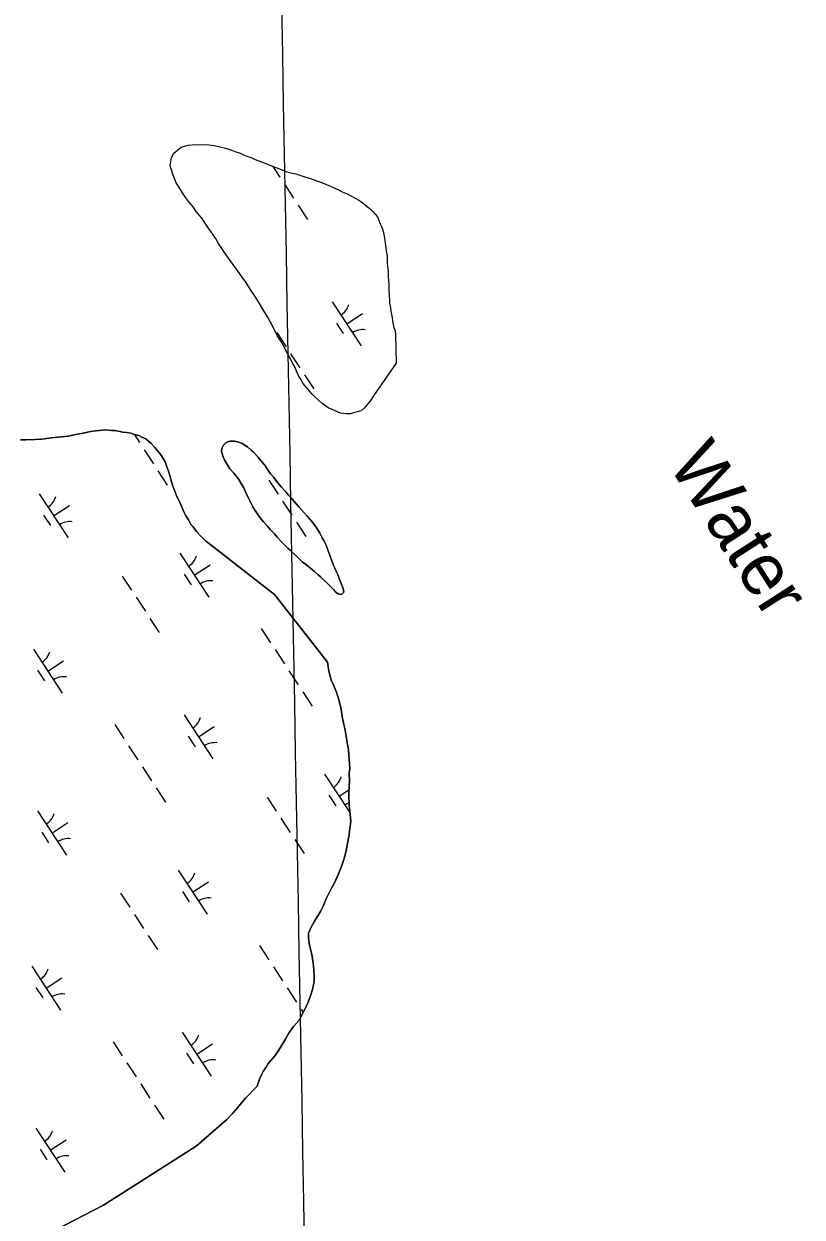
# Model space of a CAD drawing. Extents: x 3945642 to 3966284, y 206476 to 228921.
# Drawn here: x 3956647 to 3957386, y 220127 to 221259 of the extents above; entities that cross this region are included whole.
import ezdxf

# ---------------------------------------------------------------- set-up
doc = ezdxf.new("R2010")
doc.units = 0
for name, color, linetype in [('V-GRID-MAJR', 7, 'Continuous'), ('V-RIVR-IDEN', 7, 'Continuous'), ('V-TOPO-SHOR', 7, 'Continuous'), ('V-WETL-SWMP', 7, 'Continuous')]:
    doc.layers.add(name, color=color, linetype=linetype)

msp = doc.modelspace()

# ---------------------------------------------------------------- linework, layer by layer
at = {"layer": 'V-GRID-MAJR'}
msp.add_spline([(3957114.3, 209221.5), (3957056.9, 212329.8), (3956944.9, 218389.8), (3956833, 224449.7), (3956787.8, 226894.5)], degree=3, dxfattribs=at)
at = {"layer": 'V-TOPO-SHOR'}
msp.add_line((3956884.6, 220717.6), (3956821.6, 220766.8), dxfattribs=at)
for points in [[(3957000.3, 220937.3), (3956978.8, 220906.3), (3956975.2, 220901), (3956972.9, 220898.3), (3956969.9, 220894.7), (3956967, 220892), (3956963.4, 220891), (3956959.8, 220890), (3956956.8, 220889.3), (3956952.9, 220889.3), (3956947.3, 220889.9), (3956942.3, 220891.9), (3956939.3, 220893.2), (3956935.7, 220894.8), (3956929.8, 220899.1), (3956923.1, 220905.3), (3956920.5, 220907.9), (3956916.8, 220911.8), (3956914.9, 220914.1), (3956911.5, 220918.4), (3956909.9, 220921.3), (3956907.5, 220925.6), (3956905.5, 220929.8), (3956904.2, 220933.1), (3956902.2, 220937.1), (3956896.9, 220946.6), (3956891.6, 220956.8), (3956887.2, 220963.6), (3956884.6, 220968.9), (3956880.9, 220976.1), (3956877.9, 220981.4), (3956873.6, 220988.6), (3956870.3, 220993.8), (3956865.6, 221001.4), (3956862.3, 221006.6), (3956857.7, 221013.8), (3956854.7, 221018.1), (3956851.7, 221022), (3956847, 221028.6), (3956843.4, 221033.5), (3956838.7, 221040), (3956835.8, 221044.3), (3956831.4, 221050.9), (3956828.5, 221055.8), (3956822.1, 221065.3), (3956818.8, 221070.2), (3956815.5, 221074.8), (3956810.2, 221081.4), (3956807.5, 221085.6), (3956803.2, 221090.5), (3956800.6, 221094.1), (3956796.6, 221100), (3956793.9, 221104.6), (3956791.3, 221108.6), (3956788.3, 221115.8), (3956786.6, 221121.7), (3956785.6, 221124.7), (3956786.2, 221128.6), (3956786.9, 221132.6), (3956789.1, 221136.5), (3956792.4, 221139.5), (3956796, 221142.2), (3956799.3, 221143.2), (3956802.6, 221144.2), (3956809.2, 221144.9), (3956813.8, 221144.6), (3956817.4, 221144.9), (3956822.7, 221144.6), (3956827.3, 221144), (3956832.9, 221142.7), (3956838.2, 221141.4), (3956841.4, 221140.5), (3956848, 221137.9), (3956851.3, 221136.9), (3956856, 221134.6), (3956859.3, 221133.6), (3956863.2, 221132.3), (3956866.2, 221130.7), (3956871.5, 221128.8), (3956878.1, 221126.2), (3956883.3, 221123.9), (3956887, 221122.6), (3956893.6, 221120.3), (3956896.5, 221119), (3956901.8, 221117.8), (3956904.8, 221117.1), (3956908.7, 221115.8), (3956915.3, 221113.6), (3956919, 221112.6), (3956923.9, 221110.7), (3956929.5, 221108.7), (3956933.1, 221107.1), (3956937.1, 221105.5), (3956941.4, 221103.8), (3956946, 221101.6)], [(3956946, 221101.6), (3956949, 221099.9), (3956953.6, 221098), (3956957.9, 221095.7), (3956964.8, 221092.1), (3956967.5, 221090.2), (3956971.4, 221086.9), (3956975.7, 221083.6), (3956978.1, 221081.3), (3956982.4, 221076.1), (3956985, 221069.5), (3956986.7, 221066.3), (3956987.7, 221062.6), (3956989.1, 221056.1), (3956989.8, 221051.1), (3956990.8, 221043.9), (3956991.5, 221039.3), (3956991.8, 221031.7), (3956992.5, 221024.5), (3956992.6, 221019.6), (3956993.3, 221011.7), (3956993.3, 221007.4), (3956993.7, 221001.1), (3956994, 220997.5), (3956994, 220994.2), (3956994.7, 220989.9), (3956995.1, 220986.7), (3956996.1, 220982.1), (3956997.1, 220975.5), (3956998.1, 220971.2), (3956999.1, 220967.9), (3956999.5, 220964.3), (3957000.3, 220937.3)], [(3956821.6, 220766.8), (3956818.9, 220769), (3956814.6, 220773), (3956810.7, 220777.6), (3956807.3, 220781.8), (3956805, 220784.8), (3956803, 220788.4), (3956800.4, 220792.3), (3956799, 220795.6), (3956796, 220802.2), (3956793.4, 220807.7), (3956792, 220810.7), (3956790, 220815.6), (3956787.7, 220821.5), (3956786.4, 220825.8), (3956785.7, 220829.7), (3956784, 220834.7), (3956782.7, 220838), (3956780.7, 220843.5), (3956779, 220846.8), (3956776.7, 220850.4), (3956772.7, 220855.3), (3956770.7, 220857.6), (3956767.1, 220861.2), (3956762.4, 220865.5), (3956758.8, 220867.1), (3956755.8, 220868.7), (3956751.5, 220869.7), (3956748.2, 220870.7), (3956744, 220871.6), (3956740.7, 220871.9), (3956736.1, 220872.6), (3956733.1, 220873.2), (3956729.8, 220873.5), (3956724.2, 220874.1), (3956718.3, 220873.5), (3956714.7, 220873.1), (3956710, 220872.4), (3956703.1, 220870.7), (3956697.6, 220870), (3956688.7, 220868), (3956682.4, 220867.3), (3956672.6, 220866.3), (3956663.7, 220865.2), (3956657.4, 220864.9), (3956648.5, 220864.5), (3956643.6, 220864.5)], [(3956947.6, 220728.9), (3956946.4, 220731.8), (3956944.8, 220736.7), (3956942.4, 220741.7), (3956940.1, 220747.2), (3956937.9, 220753.2), (3956935.3, 220760.1), (3956933.3, 220765.2), (3956931.4, 220769), (3956929.9, 220771.6), (3956927.8, 220775.8), (3956924.1, 220781.6), (3956920, 220786.8), (3956915.6, 220792.1), (3956912.9, 220795.3), (3956908.2, 220800.5), (3956903.6, 220805.7), (3956900.4, 220809.4), (3956898.1, 220811.8), (3956894.9, 220815.6), (3956891.4, 220819.5), (3956887.6, 220824.1), (3956883.9, 220828.7), (3956881, 220832.3), (3956878.6, 220835.5), (3956876, 220839.5), (3956873.3, 220843.1), (3956871.2, 220845.4), (3956869.1, 220848.1), (3956864.6, 220852.7), (3956862.4, 220854.8), (3956859.1, 220857.8), (3956853.8, 220861), (3956849.7, 220862.5), (3956846.7, 220863.3), (3956842.4, 220863.2), (3956838.8, 220861.9), (3956836.3, 220859.4), (3956834.7, 220856.4), (3956834.4, 220853.4), (3956835.8, 220848.4), (3956837.4, 220844.9), (3956840.3, 220840), (3956842.3, 220836.8), (3956846.2, 220832.7), (3956850.1, 220827.8), (3956854, 220821.5), (3956855.5, 220818.9), (3956857.2, 220815), (3956860, 220809.2), (3956862.2, 220804.7), (3956864.1, 220800.9), (3956865.7, 220798.2), (3956868.7, 220793.6), (3956870.8, 220790.6), (3956874.3, 220786.5), (3956878.1, 220782.4), (3956880.6, 220779.5), (3956884.6, 220775.1), (3956887.3, 220772.1), (3956891.4, 220767.8), (3956893.9, 220765.1), (3956897.4, 220761.6), (3956899.8, 220759.3), (3956905.2, 220754.2), (3956907.6, 220752), (3956911.4, 220748.5), (3956914.6, 220746), (3956919.4, 220742), (3956922.2, 220739.8), (3956926.1, 220736.4), (3956928.3, 220734.4), (3956931.6, 220731.3), (3956934.5, 220728.7), (3956938.3, 220724.8), (3956940.6, 220722.5), (3956942.8, 220720), (3956945.2, 220718.2), (3956948.4, 220717.7), (3956950.6, 220720), (3956949.9, 220723.2), (3956947.6, 220728.9)], [(3956916.5, 220330.6), (3956919.2, 220337.6), (3956920.6, 220342.8), (3956922.2, 220349.8), (3956922.3, 220354.5), (3956922.1, 220361.2), (3956921.4, 220367.7), (3956920.8, 220371.8), (3956920.2, 220376), (3956919.1, 220379.8), (3956917.8, 220384.9), (3956917.2, 220388.1), (3956916.8, 220392.3), (3956917.1, 220396), (3956919.5, 220401.7), (3956922.7, 220407.5), (3956924.2, 220410.2), (3956926.8, 220414.3), (3956928.7, 220417.3), (3956930.9, 220421.8), (3956932, 220424.8), (3956933.4, 220428), (3956935.9, 220433.2), (3956937.7, 220436.9), (3956941.1, 220442.8), (3956943, 220446.6), (3956945.4, 220452.3), (3956946.8, 220455.6), (3956948.5, 220460.4), (3956950.1, 220465), (3956951.2, 220468.2), (3956952.6, 220474.4), (3956953.8, 220479.7), (3956955.6, 220489.5), (3956956, 220493.2), (3956957.1, 220502.1), (3956956.8, 220505.7), (3956956.4, 220508.8), (3956955.7, 220517.3), (3956955.5, 220521.2), (3956955.4, 220524.8), (3956955.1, 220529.1), (3956955.7, 220535.7), (3956955.8, 220540.5), (3956955.7, 220548), (3956956.1, 220552.2), (3956955.8, 220557.3), (3956955.4, 220565.2), (3956954.9, 220570.4), (3956953.7, 220576.7), (3956952.7, 220583.3), (3956951.4, 220590.3), (3956950.6, 220594.1), (3956949.9, 220597.4), (3956949, 220601.6), (3956948.6, 220604.8), (3956947.5, 220610), (3956946.8, 220613.5), (3956946, 220616.8), (3956944.5, 220621.8), (3956943.5, 220624.8), (3956941.5, 220629.3), (3956940.4, 220632.4), (3956938.7, 220635.8), (3956937.8, 220638.8), (3956936.5, 220643.7), (3956935.9, 220646.8), (3956935.1, 220653.5), (3956884.6, 220717.6)], [(3956868.2, 220250.8), (3956870.3, 220257.4), (3956871.6, 220260.5), (3956874, 220264.8), (3956877.2, 220269.6), (3956878.8, 220272.4), (3956883.1, 220277.5), (3956885.2, 220280), (3956888.5, 220284.7), (3956891.1, 220288.7), (3956895.3, 220296.1), (3956898.6, 220301.9), (3956902.8, 220307.6), (3956908.2, 220313.6), (3956911.1, 220319.4), (3956914.3, 220325.9), (3956916.5, 220330.6)], [(3956810.3, 220193.8), (3956839.1, 220219), (3956845.1, 220225.3), (3956849.6, 220230.4), (3956853.4, 220234.9), (3956857.1, 220239.6), (3956868.2, 220250.8)], [(3956649.6, 220100.2), (3956722.3, 220138), (3956810.3, 220193.8)]]:
    msp.add_lwpolyline(points, dxfattribs=at)
at = {"layer": 'V-WETL-SWMP'}
for p, q in [((3956883.1, 221124), (3956889.7, 221114)), ((3956894, 221107.3), (3956902.8, 221093.9)), ((3956907.2, 221087.2), (3956916, 221073.8)), ((3956939.5, 220995.5), (3956966.9, 220953.7)), ((3956953.2, 220974.6), (3956968.3, 220984.5)), ((3956886.9, 220966.3), (3956895.6, 220952.9)), ((3956943.5, 220975.4), (3956950, 220965.4)), ((3956900, 220946.2), (3956908.8, 220932.9)), ((3956913.2, 220926.2), (3956921.9, 220912.8)), ((3956751.3, 220869.8), (3956756.5, 220861.8)), ((3956760.9, 220855.1), (3956769.7, 220841.7)), ((3956774, 220835), (3956782.8, 220821.6)), ((3956879.3, 220826.3), (3956888, 220812.9)), ((3956661.2, 220813.2), (3956688.6, 220771.4)), ((3956892.4, 220806.2), (3956901.2, 220792.9)), ((3956674.9, 220792.3), (3956690, 220802.2)), ((3956665.2, 220793.1), (3956671.8, 220783.1)), ((3956905.6, 220786.2), (3956914.3, 220772.8)), ((3956794.8, 220757), (3956822.2, 220715.2)), ((3956808.5, 220736.1), (3956823.6, 220745.9)), ((3956740.1, 220735.2), (3956748.9, 220721.8)), ((3956798.8, 220736.9), (3956805.4, 220726.8)), ((3956753.3, 220715.1), (3956762.1, 220701.7)), ((3956766.4, 220695), (3956775.2, 220681.6)), ((3956872.1, 220685.3), (3956880.9, 220671.9)), ((3956655.7, 220665.8), (3956683.1, 220624)), ((3956885.3, 220665.3), (3956894, 220651.9)), ((3956669.4, 220644.9), (3956684.4, 220654.8)), ((3956659.6, 220645.7), (3956666.2, 220635.7)), ((3956898.4, 220645.2), (3956907.2, 220631.8)), ((3956911.6, 220625.1), (3956920.3, 220611.7)), ((3956798.8, 220603.3), (3956826.2, 220561.5)), ((3956733, 220594.2), (3956741.7, 220580.8)), ((3956812.5, 220582.4), (3956827.5, 220592.3)), ((3956802.7, 220583.2), (3956809.3, 220573.1)), ((3956746.1, 220574.1), (3956754.9, 220560.7)), ((3956759.3, 220554), (3956768, 220540.6)), ((3956932.3, 220547.1), (3956956.2, 220510.6)), ((3956772.4, 220534), (3956781.2, 220520.6)), ((3956877.7, 220525.2), (3956886.4, 220511.9)), ((3956936.3, 220527), (3956942.9, 220516.9)), ((3956946, 220526.2), (3956955.4, 220532.3)), ((3956659.6, 220512.2), (3956687, 220470.3)), ((3956673.3, 220491.2), (3956688.4, 220501.1)), ((3956890.8, 220505.2), (3956899.6, 220491.8)), ((3956663.6, 220492), (3956670.2, 220482)), ((3956904, 220485.1), (3956912.7, 220471.7)), ((3956793.2, 220455.9), (3956820.6, 220414.1)), ((3956806.9, 220435), (3956822, 220444.9)), ((3956738.5, 220434.1), (3956747.3, 220420.7)), ((3956797.2, 220435.8), (3956803.7, 220425.8)), ((3956751.7, 220414), (3956760.4, 220400.6)), ((3956764.8, 220393.9), (3956773.6, 220380.6)), ((3956870.5, 220384.3), (3956879.3, 220370.9)), ((3956654.1, 220364.8), (3956681.5, 220322.9)), ((3956883.6, 220364.2), (3956892.4, 220350.8)), ((3956667.8, 220343.9), (3956682.8, 220353.7)), ((3956658, 220344.7), (3956664.6, 220334.6)), ((3956896.8, 220344.1), (3956905.6, 220330.7)), ((3956909.9, 220324), (3956911.9, 220321.1)), ((3956797.1, 220302.2), (3956824.5, 220260.4)), ((3956731.3, 220293.1), (3956740.1, 220279.7)), ((3956810.8, 220281.3), (3956825.9, 220291.2)), ((3956801.1, 220282.1), (3956807.7, 220272.1)), ((3956744.5, 220273), (3956753.3, 220259.6)), ((3956757.6, 220253), (3956766.4, 220239.6)), ((3956770.8, 220232.9), (3956779.6, 220219.5)), ((3956658, 220211.1), (3956685.4, 220169.3)), ((3956671.7, 220190.2), (3956686.8, 220200)), ((3956662, 220191), (3956668.5, 220180.9))]:
    msp.add_line(p, q, dxfattribs=at)
for points in [[(3956946, 221101.6), (3956949, 221099.9), (3956953.6, 221098), (3956957.9, 221095.7), (3956964.8, 221092.1), (3956967.5, 221090.2), (3956971.4, 221086.9), (3956975.7, 221083.6), (3956978.1, 221081.3), (3956982.4, 221076.1), (3956985, 221069.5), (3956986.7, 221066.3), (3956987.7, 221062.6), (3956989.1, 221056.1), (3956989.8, 221051.1), (3956990.8, 221043.9), (3956991.5, 221039.3), (3956991.8, 221031.7), (3956992.5, 221024.5), (3956992.6, 221019.6), (3956993.3, 221011.7), (3956993.3, 221007.4), (3956993.7, 221001.1), (3956994, 220997.5), (3956994, 220994.2), (3956994.7, 220989.9), (3956995.1, 220986.7), (3956996.1, 220982.1), (3956997.1, 220975.5), (3956998.1, 220971.2), (3956999.1, 220967.9), (3956999.5, 220964.3), (3957000.3, 220937.3), (3956978.8, 220906.2), (3956975.2, 220901), (3956972.9, 220898.3), (3956969.9, 220894.7), (3956967, 220892), (3956963.4, 220891), (3956959.8, 220890), (3956956.8, 220889.3), (3956952.9, 220889.3), (3956947.3, 220889.9), (3956942.3, 220891.9), (3956939.3, 220893.2), (3956935.7, 220894.8), (3956929.8, 220899.1), (3956923.1, 220905.3), (3956920.5, 220907.9), (3956916.8, 220911.8), (3956914.9, 220914.1), (3956911.5, 220918.4), (3956909.9, 220921.3), (3956907.5, 220925.6), (3956905.6, 220929.8), (3956904.2, 220933.1), (3956902.2, 220937.1), (3956896.9, 220946.6), (3956891.6, 220956.8), (3956887.2, 220963.6), (3956884.6, 220968.9), (3956880.9, 220976.1), (3956877.9, 220981.4), (3956873.6, 220988.6), (3956870.3, 220993.8), (3956865.6, 221001.4), (3956862.3, 221006.6), (3956857.7, 221013.8), (3956854.7, 221018.1), (3956851.7, 221022), (3956847, 221028.6), (3956843.4, 221033.5), (3956838.7, 221040), (3956835.8, 221044.3), (3956831.4, 221050.9), (3956828.5, 221055.8), (3956822.1, 221065.3), (3956818.8, 221070.2), (3956815.5, 221074.8), (3956810.2, 221081.4), (3956807.5, 221085.6), (3956803.2, 221090.5), (3956800.6, 221094.1), (3956796.6, 221100), (3956793.9, 221104.6), (3956791.3, 221108.6), (3956788.3, 221115.8), (3956786.6, 221121.7), (3956785.6, 221124.7), (3956786.2, 221128.6), (3956786.9, 221132.6), (3956789.1, 221136.5), (3956792.4, 221139.5), (3956796, 221142.2), (3956799.3, 221143.2), (3956802.6, 221144.2), (3956809.2, 221144.9), (3956813.8, 221144.6), (3956817.4, 221144.9), (3956822.7, 221144.6), (3956827.3, 221144)], [(3956827.3, 221144), (3956832.9, 221142.7), (3956838.2, 221141.4), (3956841.4, 221140.4), (3956848, 221137.9), (3956851.3, 221136.9), (3956856, 221134.6), (3956859.3, 221133.6), (3956863.2, 221132.3), (3956866.2, 221130.7), (3956871.5, 221128.8), (3956878.1, 221126.2), (3956883.3, 221123.9), (3956887, 221122.6), (3956893.6, 221120.3), (3956896.5, 221119), (3956901.8, 221117.8), (3956904.8, 221117.1), (3956908.7, 221115.8), (3956915.3, 221113.6), (3956919, 221112.6), (3956923.9, 221110.7), (3956929.5, 221108.7), (3956933.1, 221107.1), (3956937.1, 221105.5), (3956941.4, 221103.8), (3956946, 221101.6)], [(3956643.6, 220864.5), (3956648.5, 220864.5), (3956657.4, 220864.9), (3956663.7, 220865.2), (3956672.6, 220866.3), (3956682.4, 220867.3), (3956688.7, 220868), (3956697.6, 220870), (3956703.1, 220870.7), (3956710.1, 220872.4), (3956714.7, 220873.1), (3956718.3, 220873.5), (3956724.2, 220874.1), (3956729.8, 220873.5), (3956733.1, 220873.2), (3956736.1, 220872.6), (3956740.7, 220871.9), (3956744, 220871.6), (3956748.2, 220870.7), (3956751.5, 220869.7), (3956755.8, 220868.7), (3956758.8, 220867.1), (3956762.4, 220865.5), (3956767.1, 220861.2), (3956770.7, 220857.6), (3956772.7, 220855.3), (3956776.7, 220850.4), (3956779, 220846.8), (3956780.7, 220843.5), (3956782.7, 220838), (3956784, 220834.7), (3956785.7, 220829.7), (3956786.4, 220825.8), (3956787.7, 220821.5), (3956790, 220815.6), (3956792, 220810.7), (3956793.4, 220807.7), (3956796, 220802.2), (3956799, 220795.6), (3956800.4, 220792.3), (3956803, 220788.4), (3956805, 220784.8), (3956807.3, 220781.8), (3956810.7, 220777.6), (3956814.6, 220773), (3956818.9, 220769), (3956821.6, 220766.8), (3956884.6, 220717.6), (3956935.1, 220653.5), (3956935.9, 220646.8), (3956936.5, 220643.7), (3956937.8, 220638.8), (3956938.7, 220635.8), (3956940.4, 220632.4), (3956941.5, 220629.3), (3956943.5, 220624.8), (3956944.5, 220621.8), (3956946, 220616.8), (3956946.8, 220613.5), (3956947.5, 220610), (3956948.6, 220604.8), (3956949, 220601.6)], [(3956949, 220601.6), (3956949.9, 220597.4), (3956950.6, 220594.1), (3956951.4, 220590.3), (3956952.7, 220583.3), (3956953.7, 220576.7), (3956954.9, 220570.4), (3956955.4, 220565.2), (3956955.8, 220557.3), (3956956.1, 220552.2), (3956955.7, 220548), (3956955.8, 220540.5), (3956955.7, 220535.7), (3956955.1, 220529.1), (3956955.4, 220524.8), (3956955.5, 220521.2), (3956955.7, 220517.3), (3956956.4, 220508.8), (3956956.8, 220505.7), (3956957.1, 220502.1), (3956956, 220493.2), (3956955.6, 220489.5), (3956953.8, 220479.7), (3956952.6, 220474.4), (3956951.2, 220468.2), (3956950.1, 220465), (3956948.5, 220460.4), (3956946.8, 220455.6), (3956945.4, 220452.3), (3956943, 220446.6), (3956941.1, 220442.8), (3956937.7, 220436.9), (3956935.9, 220433.2), (3956933.4, 220428), (3956932, 220424.8), (3956930.9, 220421.8), (3956928.7, 220417.3), (3956926.8, 220414.3), (3956924.2, 220410.2), (3956922.7, 220407.5), (3956919.5, 220401.7), (3956917.1, 220396), (3956916.8, 220392.3), (3956917.2, 220388.1), (3956917.8, 220384.9), (3956919.1, 220379.8), (3956920.2, 220376), (3956920.8, 220371.8), (3956921.4, 220367.7), (3956922.1, 220361.2), (3956922.3, 220354.5), (3956922.2, 220349.8), (3956920.6, 220342.8), (3956919.2, 220337.6), (3956916.5, 220330.6), (3956914.3, 220325.9), (3956911.1, 220319.4), (3956908.2, 220313.6), (3956902.8, 220307.6), (3956898.6, 220301.9), (3956895.3, 220296.1), (3956891.1, 220288.7), (3956888.5, 220284.7), (3956885.2, 220280), (3956883.1, 220277.5), (3956878.8, 220272.4), (3956877.2, 220269.6), (3956874, 220264.8), (3956871.6, 220260.5), (3956870.3, 220257.4), (3956868.2, 220250.8), (3956857.1, 220239.6), (3956853.4, 220234.9), (3956849.6, 220230.4), (3956845.1, 220225.3), (3956839.1, 220219), (3956810.3, 220193.8), (3956722.3, 220138), (3956649.6, 220100.2)]]:
    msp.add_lwpolyline(points, dxfattribs=at)
msp.add_lwpolyline([(3956947.6, 220728.9), (3956949.9, 220723.2), (3956950.6, 220720), (3956948.4, 220717.7), (3956945.2, 220718.2), (3956942.8, 220720), (3956940.6, 220722.5), (3956938.3, 220724.8), (3956934.5, 220728.7), (3956931.6, 220731.3), (3956928.3, 220734.4), (3956926.1, 220736.4), (3956922.2, 220739.8), (3956919.4, 220742), (3956914.6, 220746), (3956911.4, 220748.5), (3956907.6, 220752), (3956905.2, 220754.2), (3956899.8, 220759.3), (3956897.4, 220761.6), (3956893.9, 220765.1), (3956891.4, 220767.8), (3956887.3, 220772.1), (3956884.6, 220775.1), (3956880.6, 220779.5), (3956878.1, 220782.4), (3956874.3, 220786.5), (3956870.8, 220790.6), (3956868.7, 220793.6), (3956865.7, 220798.2), (3956864.1, 220800.9), (3956862.2, 220804.7), (3956860, 220809.2), (3956857.2, 220815), (3956855.5, 220818.9), (3956854, 220821.5), (3956850.1, 220827.8), (3956846.2, 220832.7), (3956842.3, 220836.8), (3956840.3, 220840), (3956837.4, 220844.9), (3956835.8, 220848.4), (3956834.4, 220853.4), (3956834.7, 220856.4), (3956836.3, 220859.4), (3956838.8, 220861.9), (3956842.4, 220863.2), (3956846.7, 220863.3), (3956849.7, 220862.5), (3956853.8, 220861), (3956859.1, 220857.8), (3956862.4, 220854.8), (3956864.6, 220852.7), (3956869.1, 220848.1), (3956871.2, 220845.4), (3956873.3, 220843.1), (3956876, 220839.5), (3956878.6, 220835.5), (3956881, 220832.3), (3956883.9, 220828.7), (3956887.6, 220824.1), (3956891.4, 220819.5), (3956894.9, 220815.6), (3956898.1, 220811.8), (3956900.4, 220809.4), (3956903.6, 220805.7), (3956908.2, 220800.5), (3956912.9, 220795.3), (3956915.6, 220792.1), (3956920, 220786.8), (3956924.1, 220781.6), (3956927.8, 220775.8), (3956929.9, 220771.6), (3956931.4, 220769), (3956933.3, 220765.2), (3956935.3, 220760.1), (3956937.9, 220753.2), (3956940.1, 220747.2), (3956942.4, 220741.7), (3956944.8, 220736.7), (3956946.4, 220731.8)], close=True, dxfattribs=at)
for centre, start, end in [((3956938.3, 220997.8), 302.4575, 344.0011), ((3956968.5, 220951.6), 82.4574, 124.0011), ((3956660, 220815.5), 302.4575, 344.0011), ((3956690.3, 220769.3), 82.4574, 124.0011), ((3956793.6, 220759.3), 302.4575, 344.0011), ((3956823.9, 220713.1), 82.4574, 124.0011), ((3956654.4, 220668.2), 302.4575, 344.0011), ((3956684.7, 220622), 82.4574, 124.0011), ((3956797.5, 220605.6), 302.4575, 344.0011), ((3956827.8, 220559.4), 82.4574, 124.0011), ((3956931.1, 220549.4), 302.4575, 344.0011), ((3956961.4, 220503.2), 109.3174, 124.0011), ((3956658.4, 220514.5), 302.4575, 344.0011), ((3956688.7, 220468.3), 82.4574, 124.0011), ((3956792, 220458.2), 302.4575, 344.0011), ((3956822.2, 220412), 82.4574, 124.0011), ((3956652.8, 220367.1), 302.4575, 344.0011), ((3956683.1, 220320.9), 82.4574, 124.0011), ((3956795.9, 220304.6), 302.4575, 344.0011), ((3956826.2, 220258.3), 82.4574, 124.0011), ((3956656.8, 220213.4), 302.4575, 344.0011), ((3956687, 220167.2), 82.4574, 124.0011)]:
    msp.add_arc(centre, 17.6, start, end, dxfattribs=at)

# ---------------------------------------------------------------- texts
at = {"layer": 'V-RIVR-IDEN'}
msp.add_text('Water', height=50, rotation=302.6757, dxfattribs=at).set_placement((3957257.4, 220841.8))

doc.saveas('drawing.dxf')
